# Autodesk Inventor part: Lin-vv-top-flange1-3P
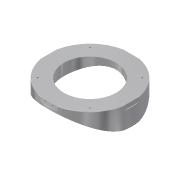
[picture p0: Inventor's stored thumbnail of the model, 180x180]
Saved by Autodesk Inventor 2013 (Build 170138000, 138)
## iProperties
Created: 2012-05
Part Number: Lin-vv-top-flange1-3P
Material: Stainless Steel, 316
Description: VACUUM VESSEL TOP FLANGE
Document SubType Name: Modeling
Designer: Henneborn
Manufacturer: Standard
Standards Organization: Custom
Mass: 28424.5 g
Surface Area: 2798.76 cm^2
Volume: 3598.04 cm^3
Density: 7.9 g/cm^3
Rohmasse: 16" O.D. x 3,0"
Author: vm
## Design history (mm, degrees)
sketch "Sketch1"
  geometry: C1 r 317.5 at (0, 0); C2 r 196.85 at (0, 0); 1 further point
  constraints: 2 centre point, 1 coincident
  dimensions: "d0" = 635 diameter of C1; "d1" = 393.7 diameter of C2
extrude "Extrusion1" new body sketch "Sketch1" stored distance "d2" = 160.02; taper "d3" = 0 deg
sketch "Sketch2"
  geometry: L1 (-317.5, 80.01)-(317.5, 80.01) reference; L2 (317.5, -80.01)-(-317.5, -80.01) reference; C1 r 482.6 at (0, 448.31); 1 further point
  constraints: 1 centre point, 1 midpoint, 1 vertical alignment
  dimensions: "d4" = 965.2 diameter of C1; "d5" = 45.72 distance edge to line of C1 L2
extrude "Extrusion2" cut sketch "Sketch2" stored distance "d6" = 76.2; taper "d7" = 0 deg
sketch "Sketch6"
  geometry: L1 (-311.15, 63.182)-(-311.15, -63.182); L2 (0, -444.5)-(0, 444.5) reference; A1 r 317.5 centre (0, 0) between (-311.15, 63.182) and (-311.15, -63.182) reference; 1 further point
  constraints: 2 end point, 2 point on circle
  dimensions: "d98" = 311.15 distance between parallel lines of L2 L1
extrude "Extrusion5" cut sketch "Sketch6" distance "d26" = 31.75; taper "d27" = 0 deg
sketch "Sketch7"
  geometry: L1 (31.75, 126.363)-(31.75, 0) reference; L2 (63.755, 63.182)-(-160.28, 63.182) reference; 2 further points
  constraints: 1 vertical alignment
  dimensions: "d28" = 12.7 distance from line of L1 point (19.05, 34.607); "d29" = 28.575 distance from line of L2 point (19.05, 91.757); "d30" = 28.575 distance from line of L2 point (19.05, 34.607) (= d29)
hole "Hole2" sketch "Sketch7" at (19.05, 91.757), (19.05, 34.607) diameter "d31" = 8.382; stored, may be unused: countersink angle "d35" = 82 deg, drill point angle "d37" = 118 deg; dims "d32" = 17.78, "d33" = 9.525, "d34" = 6.35, "d36" = 21.59
pattern_circular "Circular Pattern2" dims angle "d40" = 360 deg
chamfer "Chamfer1" distance "d55" = 1.5875; stored, may be unused: second distance "d56" = 3.175, angle "d57" = 45 deg
sketch "Sketch15"
  geometry: L1 (444.5, 0)-(-444.5, 0) reference; L2 (0, 0)-(-197.566, -197.566); C1 r 196.85 at (0, 0) reference; 1 further point
  constraints: 2 coincident, 2 end point
  dimensions: "d120" = 45 deg angle of L2 L1; "d121" = 279.4 distance of C1.centre point (-197.566, -197.566)
hole "Hole7" sketch "Sketch15" at (-197.566, -197.566) diameter "d122" = 8.382; stored, may be unused: countersink angle "d126" = 82 deg, drill point angle "d128" = 118 deg; dims "d123" = 17.78, "d124" = 9.525, "d125" = 6.35, "d127" = 21.59
pattern_circular "Circular Pattern7" dims angle "d130" = 360 deg
body "Solid1"
